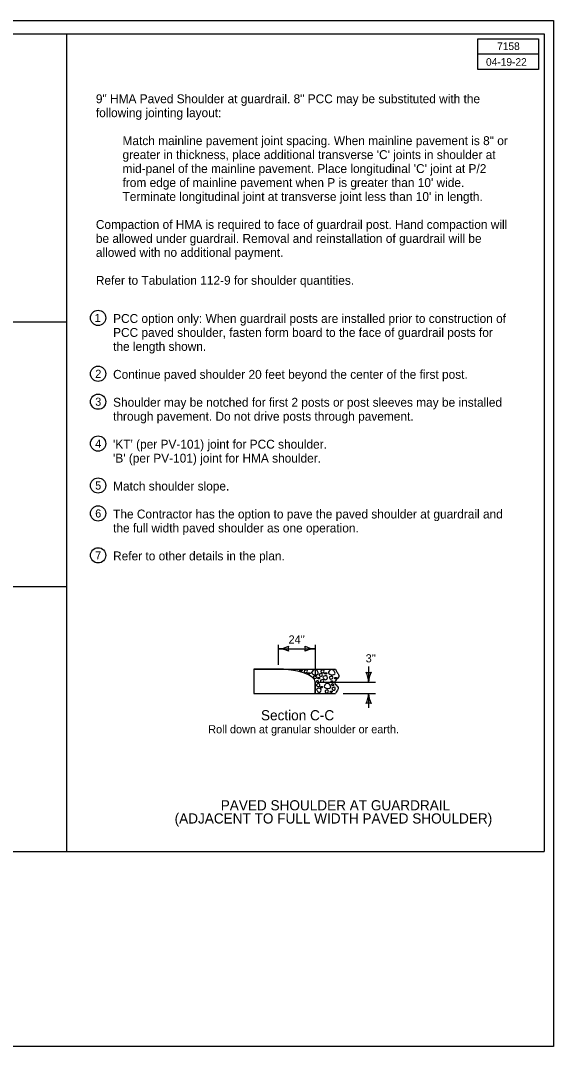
# Model space of a CAD drawing. Extents: x 6410 to 81668, y 3928 to 11667.
# Drawn here: x 12218 to 13268, y 7924 to 9944 of the extents above; entities that cross this region are included whole.
import ezdxf

# ---------------------------------------------------------------- set-up
doc = ezdxf.new("R2010")
doc.units = 0
for name, color, linetype in [('dsnCellElements', 7, 'Continuous'), ('dsnNonPlotable', 7, 'Continuous'), ('dsnShtPlotShapeBatchPrint', 7, 'Continuous'), ('dsnStdBlockModified', 7, 'Continuous'), ('dsnStdNameDate', 7, 'Continuous'), ('Level 11', 7, 'Continuous'), ('Level 3', 7, 'Continuous'), ('Level 7', 7, 'Continuous'), ('Level 8', 7, 'Continuous'), ('Level 9', 7, 'Continuous')]:
    doc.layers.add(name, color=color, linetype=linetype)

msp = doc.modelspace()

# ---------------------------------------------------------------- linework, layer by layer
at = {"layer": 'dsnNonPlotable'}
for p, q in [((10153.2, 9917.9), (13248.9, 9917.9)), ((13248.9, 9917.9), (13248.9, 8307.9)), ((10153.2, 8307.9), (13248.9, 8307.9))]:
    msp.add_line(p, q, dxfattribs=at)
at = {"layer": 'dsnShtPlotShapeBatchPrint'}
for p, q in [((12725.6, 8675.7), (12725.6, 8715.1)), ((12725.6, 8707.1), (12798.2, 8707.1)), ((12798.2, 8715.1), (12798.2, 8651.6)), ((12903.3, 8672), (12903.3, 8641)), ((12805, 8641), (12917.1, 8641)), ((12853, 8619.2), (12917.1, 8619.2)), ((12903.3, 8619.2), (12903.3, 8590.6))]:
    msp.add_line(p, q, dxfattribs=at)
for centre, radius, start, end in [((12725.6, 8749.6), 42.5, 270, 298.0725), ((12725.6, 8664.6), 42.5, 61.9275, 90), ((12761.3, 8707.1), 16.4, 162.2666, 197.7334), ((12762.5, 8707.1), 16.4, 342.2666, 17.7334), ((12798.2, 8749.6), 42.5, 241.9275, 270), ((12798.2, 8664.6), 42.5, 90, 118.0725), ((12903.3, 8676.7), 16.4, 252.2666, 287.7334), ((12860.8, 8641), 42.5, 0, 28.0725), ((12945.8, 8641), 42.5, 151.9275, 180), ((12860.8, 8619.2), 42.5, 331.9275, 360), ((12945.8, 8619.2), 42.5, 180, 208.0725), ((12903.3, 8583.6), 16.4, 72.2666, 107.7334)]:
    msp.add_arc(centre, radius, start, end, dxfattribs=at)
at = {"layer": 'dsnStdBlockModified'}
for p, q in [((13248.9, 9917.9), (13248.9, 9917.9)), ((12677.2, 8667.2), (12677.2, 8619.2)), ((12677.2, 8667.2), (12720.3, 8667.1)), ((12720.3, 8667.1), (12838, 8667.1)), ((12798.2, 8641), (12798.2, 8619.2)), ((12677.2, 8619.2), (12798.2, 8619.2)), ((12798.2, 8619.2), (12838, 8619.2))]:
    msp.add_line(p, q, dxfattribs=at)
msp.add_lwpolyline([(13238, 9907.9), (13238, 9847.9), (13118.3, 9847.9), (13118.3, 9907.9), (13238, 9907.9), (13238, 9877.9), (13118.3, 9877.9)], dxfattribs=at)
msp.add_ellipse((12720.3, 8641), major_axis=(77.9, 0), ratio=0.335273, start_param=0, end_param=1.570796, dxfattribs=at)
msp.add_spline([(12838, 8667.1), (12839.4, 8663.9), (12841.3, 8660.8), (12843.2, 8657.7), (12844.6, 8654.7), (12844.7, 8652.9), (12844, 8651.2), (12841.2, 8647.7), (12838, 8644.2), (12836.9, 8642.5), (12836.6, 8641.6), (12836.5, 8640.7), (12836.5, 8640.3), (12836.8, 8639.1), (12837.8, 8637.5), (12840.8, 8634.3), (12843.3, 8631.1), (12843.7, 8629.6), (12843.6, 8628.8), (12843.5, 8628.4), (12843.3, 8628), (12838, 8619.2)], degree=3, dxfattribs=at)
at = {"layer": 'dsnStdNameDate'}
for points in [[(12791.2, 8659.7), (12791, 8660.2), (12791.5, 8659.8), (12793.4, 8666.2), (12801.7, 8666.5), (12804.4, 8659.3), (12804.6, 8658.5), (12799.8, 8654.7), (12793.1, 8656.9), (12791.5, 8659.2), (12791.2, 8659.7)], [(12824.2, 8659.7), (12823.9, 8660.2), (12824.4, 8659.8), (12826.3, 8666.2), (12834.6, 8666.5), (12837.3, 8659.3), (12837.6, 8658.5), (12832.7, 8654.7), (12826, 8656.9), (12824.4, 8659.2), (12824.2, 8659.7)], [(12769.9, 8662.9), (12770.8, 8662.8), (12771.3, 8662.8), (12773.7, 8665.2), (12769.7, 8666), (12766.2, 8663.8), (12769.1, 8663.1), (12769.9, 8662.9)], [(12776.4, 8663.4), (12776.4, 8664), (12776.8, 8663.8), (12781.3, 8666.5), (12783.7, 8663.3), (12781.6, 8659.3), (12776.5, 8660.3), (12776.3, 8662.8), (12776.4, 8663.4)], [(12785.6, 8657.4), (12786.4, 8657.3), (12786.9, 8657.3), (12789.4, 8659.7), (12785.3, 8660.5), (12781.9, 8658.3), (12784.7, 8657.6), (12785.6, 8657.4)], [(12794.7, 8652.2), (12794.8, 8652.8), (12795.1, 8652.6), (12799.7, 8655.3), (12802.1, 8652.1), (12800, 8648), (12794.9, 8649.1), (12794.7, 8651.6), (12794.7, 8652.2)], [(12804.9, 8648.2), (12805.7, 8648), (12806.2, 8648), (12808.6, 8650.4), (12804.6, 8651.2), (12801.1, 8649.1), (12804, 8648.4), (12804.9, 8648.2)], [(12805.8, 8656.3), (12805.8, 8656.9), (12806.2, 8656.7), (12810.7, 8659.4), (12813.1, 8656.1), (12811, 8652.1), (12805.9, 8653.2), (12805.7, 8655.7), (12805.8, 8656.3)], [(12808.6, 8644.5), (12808.7, 8645), (12809, 8644.9), (12813.6, 8647.5), (12816, 8644.3), (12813.8, 8640.3), (12808.8, 8641.4), (12808.6, 8643.9), (12808.6, 8644.5)], [(12809.3, 8663.4), (12809.3, 8664), (12809.7, 8663.8), (12814.3, 8666.5), (12816.7, 8663.3), (12814.5, 8659.3), (12809.4, 8660.3), (12809.3, 8662.8), (12809.3, 8663.4)], [(12813.8, 8650.3), (12813.3, 8651.4), (12813.4, 8651.8), (12818, 8654.7), (12822, 8652.8), (12823.1, 8647.5), (12816.9, 8644.8), (12814.4, 8649.1), (12813.8, 8650.3)], [(12818.5, 8657.4), (12819.3, 8657.3), (12819.9, 8657.3), (12822.3, 8659.7), (12818.3, 8660.5), (12814.8, 8658.3), (12817.6, 8657.6), (12818.5, 8657.4)], [(12826, 8650.9), (12826.1, 8651.5), (12826.4, 8651.3), (12831, 8654), (12833.4, 8650.7), (12831.3, 8646.7), (12826.2, 8647.8), (12826, 8650.3), (12826, 8650.9)], [(12837.8, 8648.2), (12838.6, 8648), (12839.2, 8648), (12841.6, 8650.4), (12837.6, 8651.2), (12834.1, 8649.1), (12836.9, 8648.4), (12837.8, 8648.2)], [(12800.1, 8642.5), (12799.7, 8643), (12800.1, 8643.4), (12804.4, 8644.7), (12805.7, 8641.2), (12802.5, 8640.4), (12800.5, 8642), (12800.1, 8642.5)], [(12801.3, 8625.7), (12800.7, 8626.9), (12800.9, 8627.3), (12805.4, 8630.2), (12809.5, 8628.3), (12810.5, 8623), (12804.4, 8620.3), (12801.9, 8624.6), (12801.3, 8625.7)], [(12800.9, 8636.3), (12800.9, 8636.9), (12801.3, 8636.7), (12805.8, 8639.4), (12808.2, 8636.2), (12806.1, 8632.1), (12801, 8633.2), (12800.8, 8635.7), (12800.9, 8636.3)], [(12810.1, 8630.3), (12810.9, 8630.1), (12811.5, 8630.1), (12813.9, 8632.5), (12809.9, 8633.4), (12806.4, 8631.2), (12809.2, 8630.5), (12810.1, 8630.3)], [(12815.7, 8632.5), (12815.5, 8633), (12816, 8632.7), (12817.9, 8639.1), (12826.2, 8639.4), (12828.9, 8632.1), (12829.1, 8631.3), (12824.3, 8627.6), (12817.6, 8629.7), (12816, 8632.1), (12815.7, 8632.5)], [(12817.6, 8623.8), (12817.7, 8624.3), (12818, 8624.2), (12822.6, 8626.8), (12825, 8623.6), (12822.8, 8619.6), (12817.8, 8620.7), (12817.6, 8623.2), (12817.6, 8623.8)], [(12828.8, 8642.1), (12828.4, 8642.6), (12828.7, 8642.9), (12833, 8644.3), (12834.3, 8640.8), (12831.1, 8640), (12829.2, 8641.6), (12828.8, 8642.1)], [(12830.1, 8636), (12829.7, 8636.5), (12830, 8636.8), (12834.3, 8638.2), (12835.6, 8634.7), (12832.4, 8633.9), (12830.5, 8635.5), (12830.1, 8636)], [(12831.2, 8629.2), (12831.2, 8629.8), (12831.6, 8629.6), (12836.2, 8632.3), (12838.6, 8629), (12836.4, 8625), (12831.3, 8626.1), (12831.2, 8628.6), (12831.2, 8629.2)], [(12829.4, 8621.1), (12830.2, 8620.9), (12830.7, 8620.9), (12833.2, 8623.3), (12829.1, 8624.1), (12825.7, 8622), (12828.5, 8621.3), (12829.4, 8621.1)]]:
    msp.add_open_spline(points, degree=3, dxfattribs=at)
at = {"layer": 'Level 11'}
for p, q in [((12308.8, 8307.9), (12308.8, 9917.9)), ((12308.8, 9349.9), (10153.2, 9349.9)), ((12308.8, 8828.9), (10153.2, 8828.9))]:
    msp.add_line(p, q, dxfattribs=at)
at = {"layer": 'Level 3'}
for p, q in [((12720.3, 8667.2), (12677.2, 8667.2)), ((12677.2, 8667.2), (12677.2, 8619.2)), ((12798.2, 8619.2), (12798.2, 8641)), ((12677.2, 8619.2), (12798.2, 8619.2))]:
    msp.add_line(p, q, dxfattribs=at)
msp.add_lwpolyline([(12720.3, 8667.1), (12720.3, 8667.2)], dxfattribs=at)
msp.add_ellipse((12720.3, 8641), major_axis=(77.9, 0), ratio=0.335273, start_param=0, end_param=1.570796, dxfattribs=at)
at = {"layer": 'Level 7'}
for centre in [(12370.6, 9358.5), (12370.6, 9248.5), (12370.6, 9193.5), (12370.6, 9111), (12370.6, 9028.5), (12370.6, 8973.5), (12370.6, 8891)]:
    msp.add_circle(centre, 15, dxfattribs=at)
at = {"layer": 'Level 8'}
msp.add_lwpolyline([(10132.5, 9944), (13267.5, 9944), (13267.5, 7924), (10132.5, 7924)], close=True, dxfattribs=at)

# ---------------------------------------------------------------- texts
at = {"layer": 'dsnCellElements'}
for s, height, p in [('Section C-C', 20, (12691.4, 8566.2)), ('Roll down at granular shoulder or earth.', 16, (12587.5, 8540.6)), ('PAVED SHOULDER AT GUARDRAIL', 20, (12612.1, 8388.9)), ('(ADJACENT TO FULL WIDTH PAVED SHOULDER)', 20, (12521.3, 8363))]:
    msp.add_text(s, height=height, dxfattribs=at).set_placement(p)
at = {"layer": 'dsnShtPlotShapeBatchPrint'}
for s, p in [("24''", (12745.7, 8717.4)), ("3'' ", (12897.6, 8680.3))]:
    msp.add_text(s, height=16, dxfattribs=at).set_placement(p)
at = {"layer": 'Level 7'}
for s, height, p in [('9" HMA Paved Shoulder at guardrail. 8" PCC may be substituted with the', 17.5, (12366.2, 9781.2)), ('following jointing layout:', 17.5, (12366.2, 9753.7)), ('Match mainline pavement joint spacing. When mainline pavement is 8" or ', 17.5, (12418.7, 9698.7)), ("greater in thickness, place additional transverse 'C' joints in shoulder at ", 17.5, (12418.7, 9671.2)), ("mid-panel of the mainline pavement. Place longitudinal 'C' joint at P/2 ", 17.5, (12418.7, 9643.7)), ("from edge of mainline pavement when P is greater than 10' wide. ", 17.5, (12418.7, 9616.2)), ("Terminate longitudinal joint at transverse joint less than 10' in length.", 17.5, (12418.7, 9588.7)), ('Compaction of HMA is required to face of guardrail post. Hand compaction will ', 17.5, (12366.2, 9533.7)), ('be allowed under guardrail. Removal and reinstallation of guardrail will be ', 17.5, (12366.2, 9506.2)), ('allowed with no additional payment.', 17.5, (12366.2, 9478.7)), ('Refer to Tabulation 112-9 for shoulder quantities.', 17.5, (12366.2, 9423.7)), ('1', 16, (12363.8, 9350.5)), ('PCC option only: When guardrail posts are installed prior to construction of ', 17.5, (12400.1, 9348.6)), ('PCC paved shoulder, fasten form board to the face of guardrail posts for ', 17.5, (12400.1, 9321.1)), ('the length shown.', 17.5, (12400.1, 9293.6)), ('2', 16, (12365, 9240.5)), ('Continue paved shoulder 20 feet beyond the center of the first post.', 17.5, (12400.1, 9238.6)), ('3', 16, (12364.9, 9185.5)), ('Shoulder may be notched for first 2 posts or post sleeves may be installed ', 17.5, (12400.1, 9183.6)), ('through pavement. Do not drive posts through pavement.', 17.5, (12400.1, 9156.1)), ('4', 16, (12364.9, 9103)), ("'KT' (per PV-101) joint for PCC shoulder.", 17.5, (12400.1, 9101.1)), ("'B' (per PV-101) joint for HMA shoulder.", 17.5, (12400.1, 9073.6)), ('5', 16, (12364.8, 9020.5)), ('Match shoulder slope.', 17.5, (12400.1, 9018.6)), ('6', 16, (12364.9, 8965.5)), ('The Contractor has the option to pave the paved shoulder at guardrail and ', 17.5, (12400.1, 8963.6)), ('the full width paved shoulder as one operation.', 17.5, (12400.1, 8936.1)), ('7', 16, (12364.9, 8883)), ('Refer to other details in the plan.', 17.5, (12400.1, 8881.1))]:
    msp.add_text(s, height=height, dxfattribs=at).set_placement(p)
at = {"layer": 'Level 9'}
for s, p in [('7158', (13156.4, 9885.9)), ('04-19-22', (13134.6, 9854.9))]:
    msp.add_text(s, height=15, dxfattribs=at).set_placement(p)

doc.saveas('drawing.dxf')
